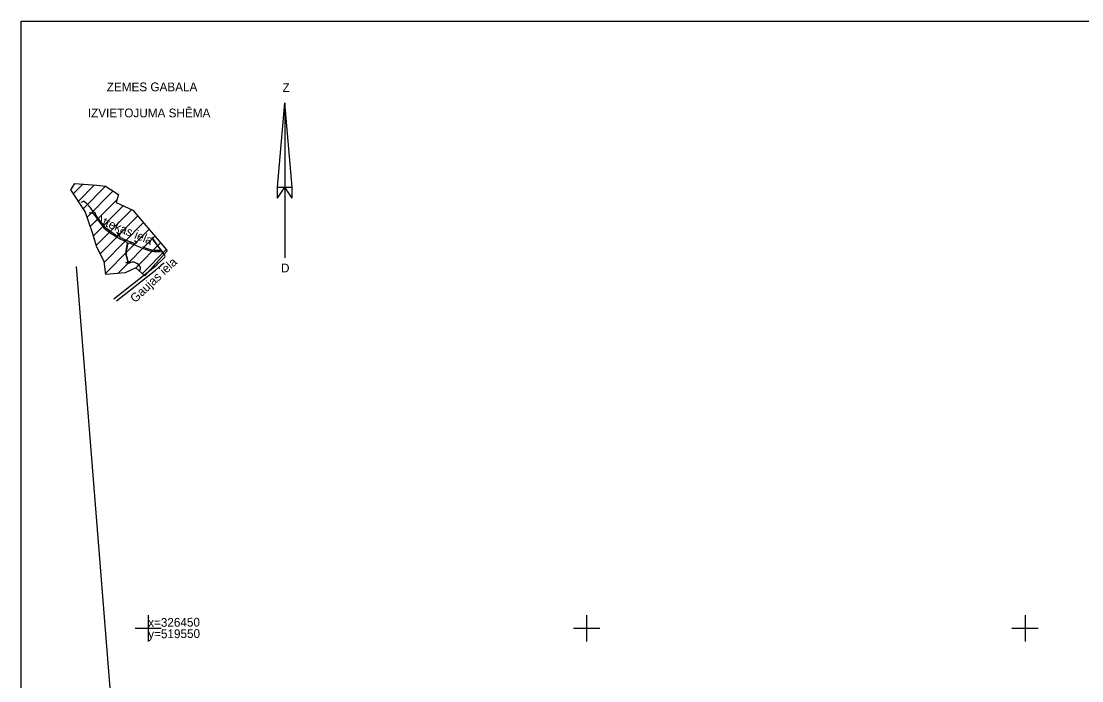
# Model space of a CAD drawing. Extents: x 519536 to 519949, y 326041 to 326519.
# Drawn here: x 519535.5 to 519656.5, y 326444 to 326519.2 of the extents above; entities that cross this region are included whole.
import ezdxf

# ---------------------------------------------------------------- set-up
doc = ezdxf.new("R2010")
doc.units = 0
for name, color, linetype in [('GEOD_ELEM_####_####_#', 7, 'Continuous'), ('GEOD_KORD_####_TKST_#', 7, 'Continuous'), ('RAMI_PLAN_####_TKST_#', 7, 'Continuous'), ('ROBZ_UZMR_####_####_#', 7, 'Continuous')]:
    doc.layers.add(name, color=color, linetype=linetype)

msp = doc.modelspace()

# ---------------------------------------------------------------- linework, layer by layer
at = {"layer": 'GEOD_ELEM_####_####_#'}
for p, q in [((519550, 326451.5), (519550, 326450)), ((519600, 326451.5), (519600, 326450)), ((519650, 326451.5), (519650, 326450)), ((519548.5, 326450), (519550, 326450)), ((519550, 326450), (519550, 326448.5)), ((519550, 326450), (519551.5, 326450)), ((519598.5, 326450), (519600, 326450)), ((519600, 326450), (519600, 326448.5)), ((519600, 326450), (519601.5, 326450)), ((519648.5, 326450), (519650, 326450)), ((519650, 326450), (519650, 326448.5)), ((519650, 326450), (519651.5, 326450))]:
    msp.add_line(p, q, dxfattribs=at)
at = {"layer": 'RAMI_PLAN_####_TKST_#'}
for p, q in [((519535.52, 326519.21), (519813.09, 326519.21)), ((519535.52, 326327.38), (519535.52, 326519.21)), ((519564.75, 326500.3), (519565.59, 326509.91)), ((519565.59, 326509.91), (519565.59, 326492.22)), ((519566.43, 326500.3), (519565.59, 326509.91)), ((519541.48, 326499.55), (519542.55, 326500.63)), ((519542.05, 326498.7), (519543.85, 326500.52)), ((519542.61, 326497.85), (519545.13, 326500.4)), ((519543.05, 326496.87), (519545.99, 326499.85)), ((519564.75, 326500.3), (519566.43, 326500.3)), ((519564.75, 326499.02), (519564.75, 326500.3)), ((519564.75, 326499.02), (519565.59, 326500.3)), ((519566.43, 326499.02), (519565.59, 326500.3)), ((519566.43, 326499.02), (519566.43, 326500.3)), ((519543.4, 326495.8), (519546.45, 326498.89)), ((519543.75, 326494.73), (519547.16, 326498.18)), ((519544.1, 326493.66), (519548.12, 326497.73)), ((519544.54, 326492.68), (519548.81, 326497.01)), ((519544.98, 326491.71), (519549.46, 326496.25)), ((519545.17, 326490.47), (519550.11, 326495.49)), ((519546.56, 326490.46), (519550.77, 326494.72)), ((519548.57, 326491.07), (519551.42, 326493.96)), ((519549.35, 326490.43), (519552.07, 326493.19))]:
    msp.add_line(p, q, dxfattribs=at)
msp.add_lwpolyline([(519552.16, 326493.03), (519549.63, 326490.19), (519548.6, 326491.08), (519547.36, 326490.53), (519545.19, 326490.33), (519544.97, 326491.81), (519544.16, 326493.46), (519543.64, 326495.07), (519542.83, 326497.52), (519541.18, 326499.99), (519541.63, 326500.71), (519544.16, 326500.5), (519545.14, 326500.4), (519546.61, 326499.45), (519546.35, 326498.56), (519548.25, 326497.67), (519552.11, 326493.14)], close=True, dxfattribs=at)
for points in [[(519548.46, 326494.22), (519548.58, 326494.1), (519548.67, 326494.03), (519548.68, 326493.97), (519548.65, 326493.87), (519548.61, 326493.85), (519548.55, 326493.84), (519548.32, 326493.92), (519548.05, 326494.02), (519547.85, 326494.09), (519547.63, 326494.18), (519547.34, 326494.3), (519547.07, 326494.42), (519546.86, 326494.52), (519546.79, 326494.6), (519546.75, 326494.69), (519546.74, 326494.78), (519546.8, 326494.91), (519546.65, 326495.01), (519546.44, 326495.11), (519546.54, 326494.96), (519546.57, 326494.78), (519546.52, 326494.74), (519546.45, 326494.74), (519546.2, 326494.9), (519545.99, 326495.03), (519545.74, 326495.21), (519545.5, 326495.39), (519545.24, 326495.59), (519545.05, 326495.77), (519544.92, 326495.94), (519544.71, 326496.18), (519544.55, 326496.41), (519544.35, 326496.69), (519544.16, 326496.96), (519544.03, 326497.14), (519543.94, 326497.26), (519544, 326497.27), (519544, 326497.33), (519543.91, 326497.37), (519543.81, 326497.45), (519543.63, 326497.67), (519543.46, 326497.9), (519543.27, 326498.12), (519543.13, 326498.28), (519543.02, 326498.39), (519542.73, 326498.6), (519542.66, 326498.69), (519542.44, 326498.59), (519542.34, 326498.56)], [(519543.26, 326497.35), (519543.43, 326497.4), (519543.59, 326497.38), (519543.72, 326497.3), (519543.89, 326497.09), (519544.03, 326496.89), (519544.23, 326496.61), (519544.44, 326496.31), (519544.75, 326495.93), (519544.96, 326495.66), (519545.18, 326495.45), (519545.49, 326495.22), (519545.82, 326494.98), (519546.15, 326494.77), (519546.49, 326494.56), (519546.85, 326494.37), (519547.24, 326494.2), (519547.47, 326494.1), (519547.55, 326494), (519547.59, 326493.86), (519547.58, 326493.64), (519547.51, 326493.3), (519547.47, 326492.94), (519547.47, 326492.59), (519547.52, 326492.29), (519547.63, 326491.85), (519547.64, 326491.7), (519547.54, 326491.61), (519547.48, 326491.74)], [(519549.06, 326490.79), (519549.13, 326490.96), (519549.12, 326491.14), (519549.05, 326491.28), (519548.89, 326491.46), (519548.72, 326491.59), (519548.55, 326491.68), (519548.39, 326491.72), (519548.17, 326491.72), (519548, 326491.69), (519547.86, 326491.64), (519547.76, 326491.58), (519547.76, 326491.58), (519547.74, 326491.74), (519547.7, 326491.92), (519547.64, 326492.14), (519547.57, 326492.38), (519547.54, 326492.61), (519547.53, 326492.86), (519547.54, 326493.09), (519547.59, 326493.34), (519547.63, 326493.56), (519547.68, 326493.79), (519547.75, 326493.89), (519547.82, 326493.94), (519547.9, 326493.93), (519548.14, 326493.84), (519548.45, 326493.72), (519548.69, 326493.61), (519548.89, 326493.53)], [(519550.55, 326494.27), (519550.65, 326494.14), (519550.94, 326493.74), (519551.21, 326493.39), (519551.4, 326493.15), (519551.39, 326493.08), (519551.11, 326493.06), (519550.68, 326493.07), (519550.42, 326493.11), (519549.94, 326493.25), (519549.51, 326493.41), (519549.45, 326493.48), (519549.47, 326493.56)], [(519551.9, 326492.57), (519551.8, 326492.7), (519551.68, 326492.87), (519551.46, 326493.17), (519551.15, 326493.57), (519550.88, 326493.93), (519550.63, 326494.28), (519550.49, 326494.48), (519550.44, 326494.59)], [(519548.93, 326493.51), (519549.25, 326493.36), (519549.89, 326493.13), (519550.24, 326493.03), (519550.67, 326492.94), (519551.06, 326492.94), (519551.35, 326492.94), (519551.55, 326492.93)], [(519551.67, 326492.78), (519551.63, 326492.83), (519551.55, 326492.93)], [(519546.08, 326487.56), (519550.74, 326491.2), (519551, 326491.43), (519551.08, 326491.51)], [(519551.08, 326491.51), (519551.15, 326491.57), (519551.51, 326491.91), (519551.73, 326492.13), (519551.9, 326492.32), (519551.94, 326492.38), (519551.92, 326492.5)], [(519551.44, 326491.37), (519551.5, 326491.42), (519551.74, 326491.64), (519551.82, 326491.64)], [(519546.39, 326487.34), (519550.82, 326490.84), (519551.19, 326491.14), (519551.44, 326491.37)]]:
    msp.add_lwpolyline(points, dxfattribs=at)
at = {"layer": 'ROBZ_UZMR_####_####_#'}
msp.add_line((519547.15, 326424.6), (519541.82, 326491.24), dxfattribs=at)

# ---------------------------------------------------------------- texts
at = {"layer": 'GEOD_KORD_####_TKST_#'}
for s, p in [('x=326450', (519550, 326450.15)), ('y=519550', (519550.01, 326448.85))]:
    msp.add_text(s, height=1, rotation=0.3993, dxfattribs=at).set_placement(p)
at = {"layer": 'RAMI_PLAN_####_TKST_#'}
for s, p in [('ZEMES GABALA', (519545.28, 326511.22)), ('Z', (519565.32, 326511.14)), ('IZVIETOJUMA SHĒMA', (519543.12, 326508.25)), ('D', (519565.15, 326490.57))]:
    msp.add_text(s, height=1, dxfattribs=at).set_placement(p)
for s, rotation, p in [('Attekas iela', 337.6313, (519543.88, 326496.32)), ('Gaujas iela', 43.2524, (519548.52, 326487.05))]:
    msp.add_text(s, height=1, rotation=rotation, dxfattribs=at).set_placement(p)

doc.saveas('drawing.dxf')
